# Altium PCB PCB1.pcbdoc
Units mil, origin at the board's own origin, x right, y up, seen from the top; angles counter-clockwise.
Board outline 3110 x 3190 mil, 2 copper layers (Top Layer, Bottom Layer); 7 components, 5 nets, 42 pads, 0 vias.
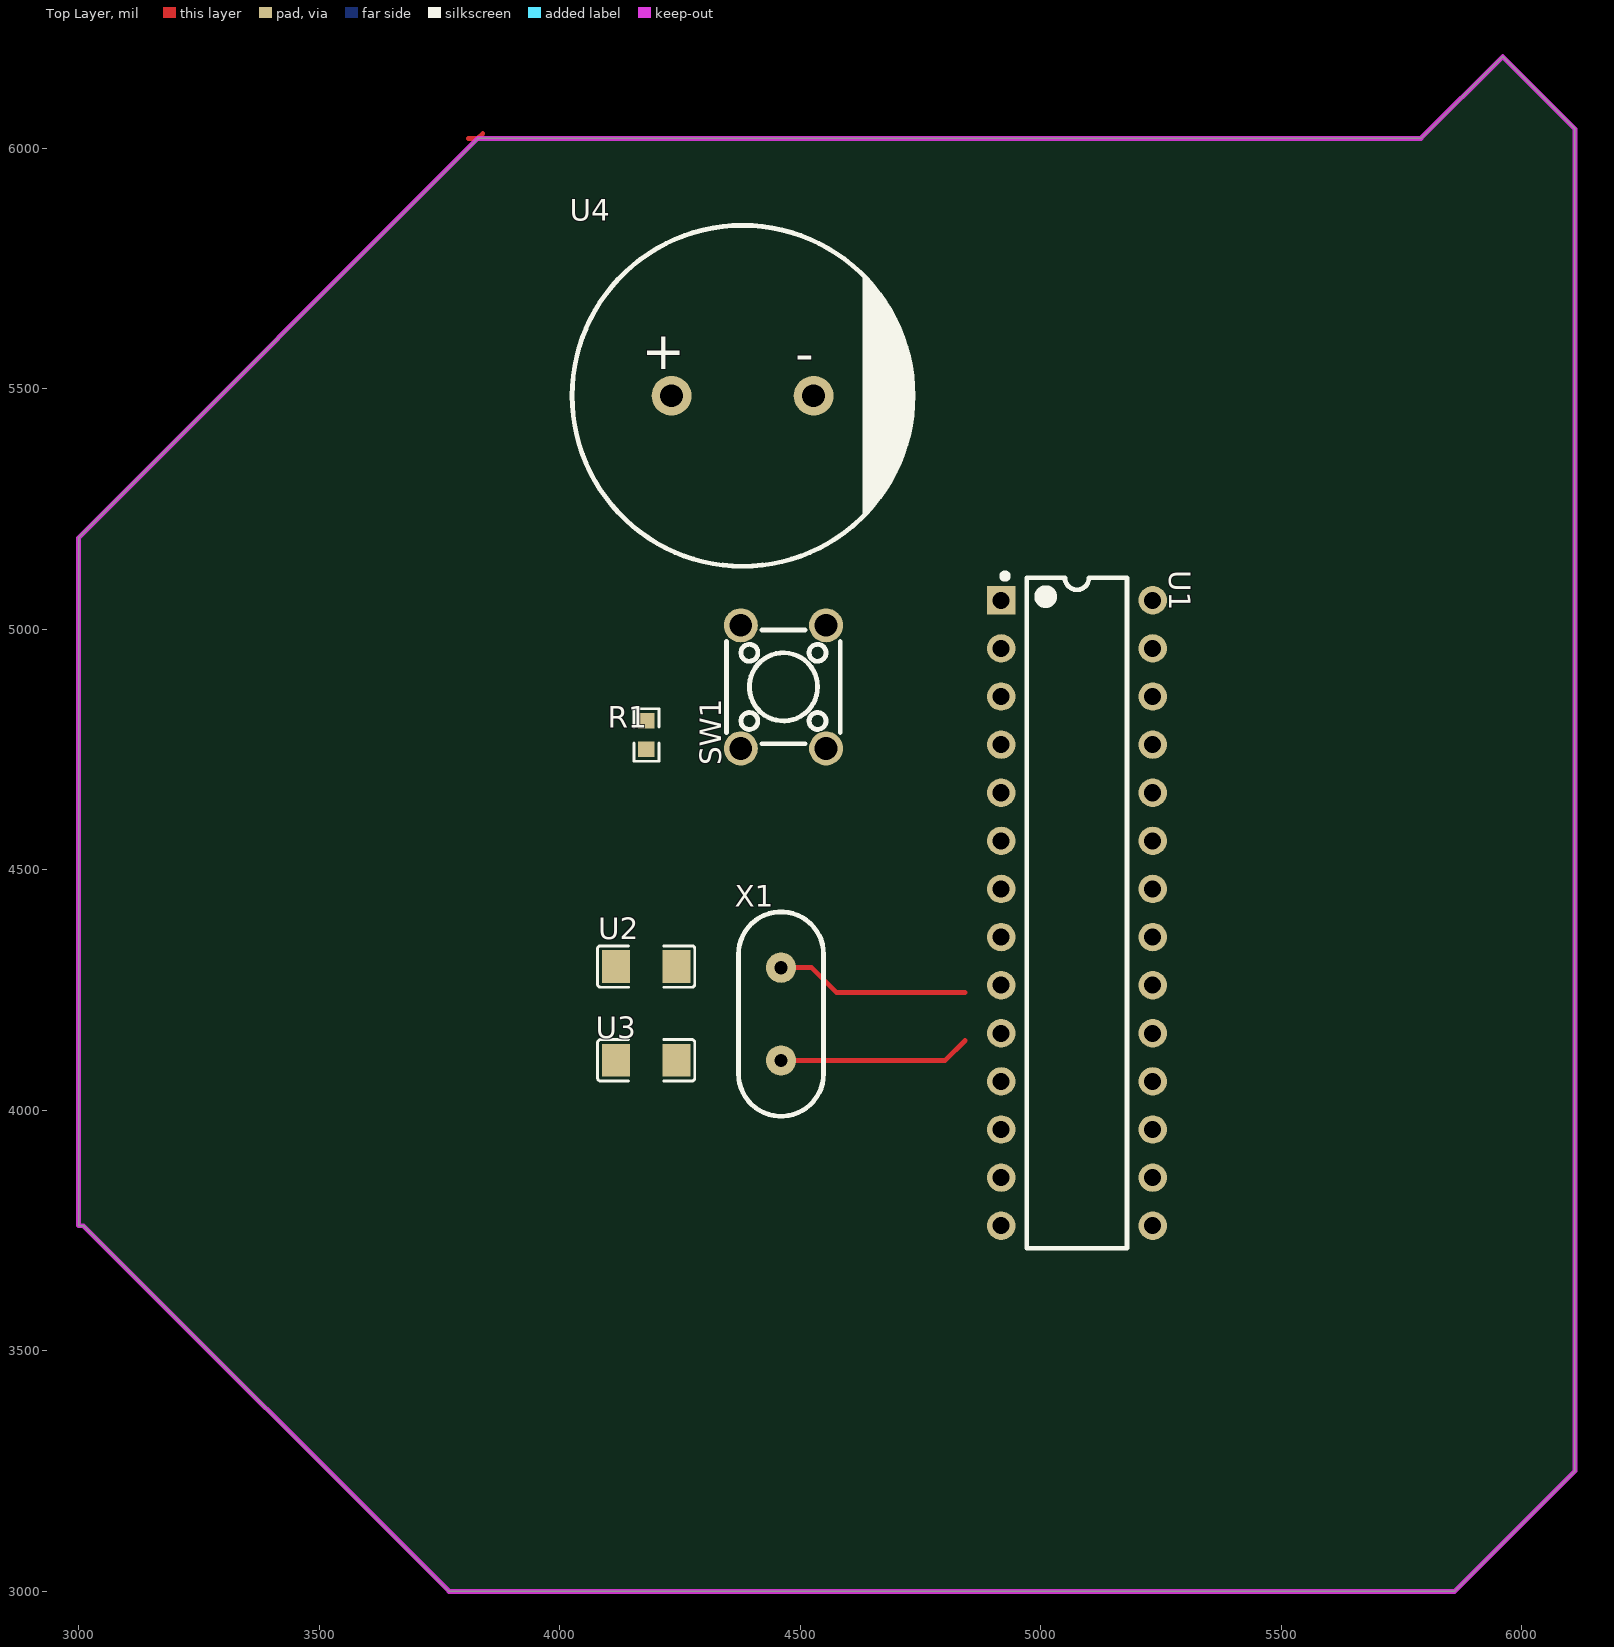
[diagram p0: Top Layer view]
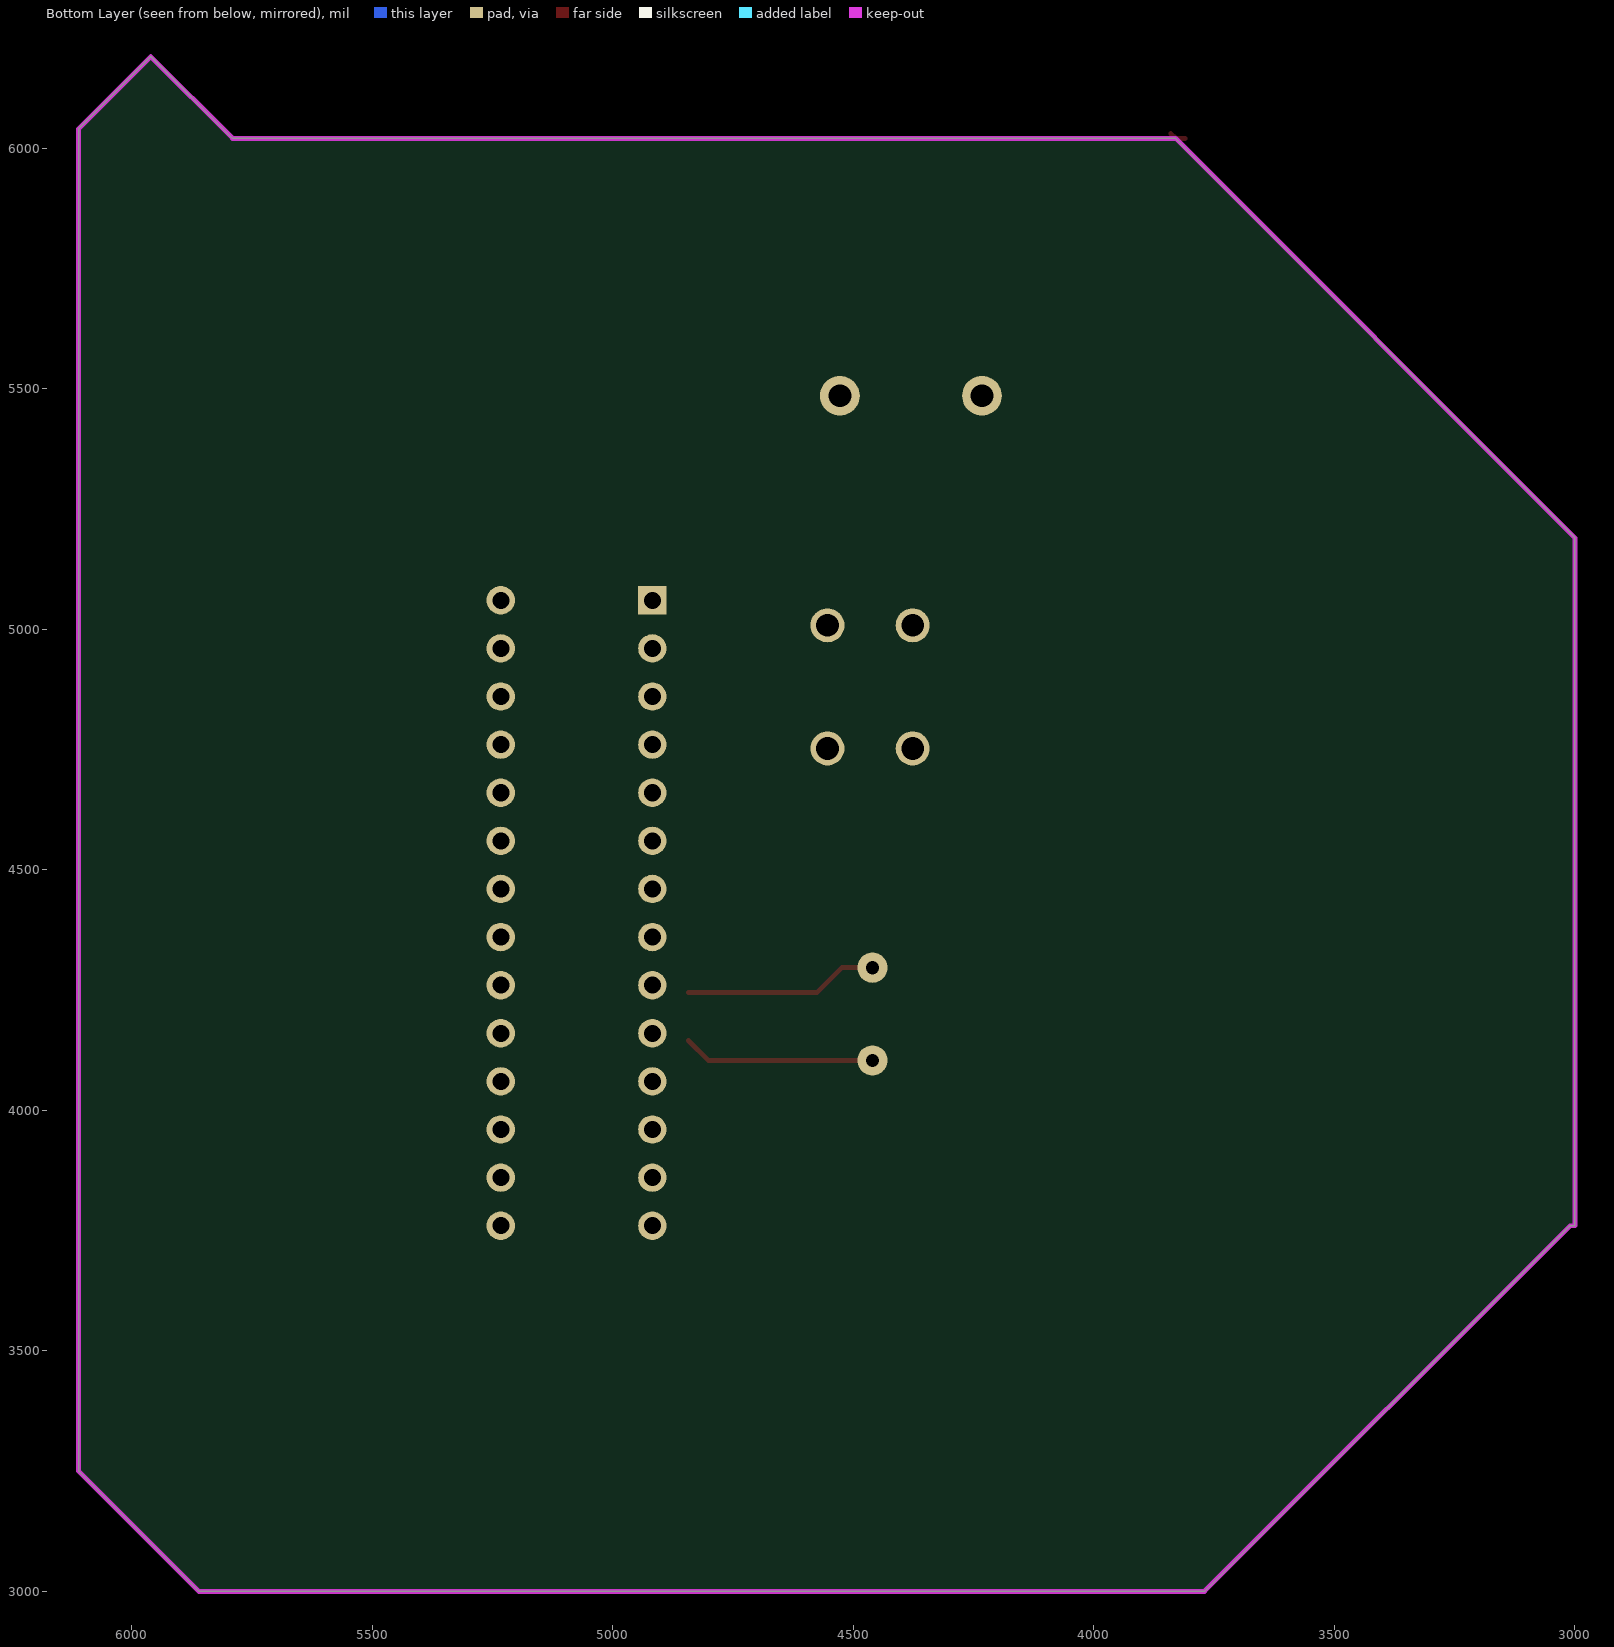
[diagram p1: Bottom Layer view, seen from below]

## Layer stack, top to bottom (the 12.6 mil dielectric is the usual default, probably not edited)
Top Layer: signal copper (thickness not stored)
Dielectric: dielectric 12.6, FR-4, Dk 4.8
Bottom Layer: signal copper (thickness not stored)

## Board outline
3000,5190 3830,6020 5790,6020 5960,6190 6110,6040 6110,3250 5860,3000 3770,3000 3010,3760 3000,3760

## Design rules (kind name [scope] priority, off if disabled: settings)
BoardOutlineClearance copperThickness1oz [All] p0: genericclearance=10 ignorepadtopadclearanceinfootprint=FALSE except(0: Arc-SplitContinuation Track-SplitContinuation SMDPad-SplitContinuation THPad-SplitContinuation Via-SplitContinuation Fill-SplitContinuation Poly-SplitContinuation Region-SplitContinuation Text-SplitContinuation; 6: Track-CutoutEdge SMDPad-CutoutEdge THPad-CutoutEdge Via-CutoutEdge Region-CutoutEdge; 11.8: Track-OutlineEdge SMDPad-OutlineEdge THPad-OutlineEdge Via-OutlineEdge Fill-OutlineEdge Region-OutlineEdge Poly-OutlineEdge Text-OutlineEdge Fill-CutoutEdge)
BoardOutlineClearance copperThickness2oz [All] p0: genericclearance=10 ignorepadtopadclearanceinfootprint=FALSE except(0: Arc-SplitContinuation Track-SplitContinuation SMDPad-SplitContinuation THPad-SplitContinuation Via-SplitContinuation Fill-SplitContinuation Poly-SplitContinuation Region-SplitContinuation Text-SplitContinuation; 6: Track-CutoutEdge SMDPad-CutoutEdge THPad-CutoutEdge Via-CutoutEdge Region-CutoutEdge; 11.8: Track-OutlineEdge SMDPad-OutlineEdge THPad-OutlineEdge Via-OutlineEdge Fill-OutlineEdge Region-OutlineEdge Poly-OutlineEdge Text-OutlineEdge Fill-CutoutEdge)
Clearance copperThickness1oz [(InNet('$1N627') OR InNet('VCC') OR InNet('GND') OR InNet('$1N402') OR InNet('$1N409'))] p1: gap=7 ignorepadtopadclearanceinfootprint=FALSE except(4: Track-Track; 6: Track-SMDPad SMDPad-SMDPad Track-THPad SMDPad-THPad THPad-THPad Track-Via SMDPad-Via THPad-Via Via-Via SMDPad-Fill THPad-Fill Via-Fill Fill-Fill Track-Region SMDPad-Region THPad-Region Via-Region Region-Region Track-Poly SMDPad-Poly THPad-Poly Via-Poly Fill-Poly Region-Poly Poly-Poly Track-Text SMDPad-Text THPad-Text Via-Text Fill-Text Region-Text Poly-Text Text-Text; 6.9: Track-Hole SMDPad-Hole THPad-Hole Via-Hole Fill-Hole Region-Hole Poly-Hole Text-Hole Sheet-Hole; 11.8: Track-Fill Fill-Region Track-Sheet SMDPad-Sheet THPad-Sheet Via-Sheet Fill-Sheet Region-Sheet Poly-Sheet Text-Sheet)
Clearance copperThickness2oz [All] p1: gap=7 ignorepadtopadclearanceinfootprint=FALSE except(6: Track-SMDPad SMDPad-SMDPad Track-THPad SMDPad-THPad THPad-THPad Track-Via SMDPad-Via THPad-Via Via-Via SMDPad-Fill THPad-Fill Via-Fill Fill-Fill Track-Region SMDPad-Region THPad-Region Via-Region Region-Region Track-Poly SMDPad-Poly THPad-Poly Via-Poly Fill-Poly Region-Poly Poly-Poly Track-Text SMDPad-Text THPad-Text Via-Text Fill-Text Region-Text Poly-Text Text-Text; 6.9: Track-Hole SMDPad-Hole THPad-Hole Via-Hole Fill-Hole Region-Hole Poly-Hole Text-Hole Sheet-Hole; 8: Track-Track; 11.8: Track-Fill Fill-Region Track-Sheet SMDPad-Sheet THPad-Sheet Via-Sheet Fill-Sheet Region-Sheet Poly-Sheet Text-Sheet)
DiffPairsRouting differentialPair [All] p1: maxuncoupledlength=10 minlimit=6 maxlimit=6 mostfreqgap=6 toplayer_minwidth=5 toplayer_prefwidth=10 toplayer_maxwidth=100 bottomlayer_minwidth=5 bottomlayer_prefwidth=10 bottomlayer_maxwidth=100
PasteMaskExpansion pasteMaskExpansion [All] p1: expansion=0
PlaneConnect innerPlane [All] p1: planeconnectstyle=Relief reliefexpansion=20 reliefentries=4 reliefconductorwidth=10 reliefairgap=10
PolygonConnect copperRegion [All] p1: connectstyle=Relief reliefentries=4 reliefconductorwidth=10 polygonreliefangle="90 Angle" airgapwidth=10
RoutingVias viaSize [All] p1: viastyle="Through Hole" holewidth=12.0078 minholewidth=11.811 maxholewidth=248.0314 width=24.0158 minwidth=19.685 maxwidth=393.7008
SolderMaskExpansion solderMaskExpansion [All] p1: useseparateexpansions=TRUE expansion=2 expansionbottom=2
Width copperThickness1oz [All] p1: maxlimit=100 minlimit=5 preferedwidth=10
Width copperThickness2oz [All] p1: maxlimit=100 minlimit=8 preferedwidth=10

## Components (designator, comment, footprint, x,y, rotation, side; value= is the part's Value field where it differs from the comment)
R1 "1k" R0603 4180,4780 r270 top
SW1 "Key_TH_6x6x6" SW-TH_4P-L6.0-W6.0-P4.50-LS6.5 4465,4880 r90 top
U1 "ATMEGA328P-PU" DIP-28_L34.6-W7.3-P2.54-LS10.2-BL 5075,4410 r270 top
U2 "FCC1206N220J102DT" C1206 4179.73,4298.79 r180 top
U3 "FCC1206N220J102DT" C1206 4179.73,4103.79 r180 top
U4 "10mF/25V" CAP-TH_BD18.0-P7.50-D0.8-FD 4380,5485 r0 top
X1 "X49SD16MSD2SC" OSC-TH_L10.0-W4.5-P5.00 4460,4200 r0 top

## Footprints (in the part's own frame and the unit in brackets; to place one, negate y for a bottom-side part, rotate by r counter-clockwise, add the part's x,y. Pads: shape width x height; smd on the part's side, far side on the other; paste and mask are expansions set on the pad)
C1206 [mm]
  rect 1.485x1.728 smd: 1(-1.593,0) 2(1.593,0)
  silkscreen extent -2.56,-1.09 2.56,1.09
CAP-TH_BD18.0-P7.50-D0.8-FD [mm]
  round 2.1 hole 1.2: 1(-3.75,0) 2(3.75,0)
  silkscreen extent -9,-9 9,9
DIP-28_L34.6-W7.3-P2.54-LS10.2-BL [mm]
  rect 1.5x1.5 hole 0.9: 1(-16.51,-4)
  round 1.5 hole 0.9: 2(-13.97,-4) 3(-11.43,-4) 4(-8.89,-4) 5(-6.35,-4) 6(-3.81,-4) 7(-1.27,-4) 8(1.27,-4) 9(3.81,-4) 10(6.35,-4) 11(8.89,-4) 12(11.43,-4) 13(13.97,-4) 14(16.51,-4) 15(16.51,4) 16(13.97,4) 17(11.43,4) 18(8.89,4) 19(6.35,4) 20(3.81,4) 21(1.27,4) 22(-1.27,4) 23(-3.81,4) 24(-6.35,4) 25(-8.89,4) 26(-11.43,4) 27(-13.97,4) 28(-16.51,4)
  silkscreen extent -17.94,-3.95 17.7,2.65
OSC-TH_L10.0-W4.5-P5.00 [mm]
  round 1.6 hole 0.7: 1(0,2.45) 2(0,-2.45)
  silkscreen extent -2.25,-5.39 2.25,5.39
R0603 [mil]
  rect 31.75x34.02 smd: 1(-29.66,0) 2(29.66,0)
  silkscreen extent -55,-26 55,26
SW-TH_4P-L6.0-W6.0-P4.50-LS6.5 [mm]
  round 1.8 hole 1.2: 1(-3.25,2.25) 2(3.25,2.25) 3(-3.25,-2.25) 4(3.25,-2.25)
  silkscreen extent -3,-3 3,3

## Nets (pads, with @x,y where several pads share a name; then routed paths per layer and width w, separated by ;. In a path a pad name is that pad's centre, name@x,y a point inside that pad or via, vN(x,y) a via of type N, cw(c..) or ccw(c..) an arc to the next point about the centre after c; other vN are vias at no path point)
$1N402: U1.9 U2.1 X1.1 | length 403.8
  Top Layer w10: X1.1 4523.54,4296.46 4575,4245 4842.52,4245
$1N409: U1.10 U3.1 X1.2 | length 399.7
  Top Layer w10: X1.2 4801.06,4103.54 4842.52,4145
$1N627: R1.2 SW1.1 U1.1
GND: SW1.3 U2.2 U3.2 U4.2
VCC: R1.1 U4.1
pads on no net: SW1.2 SW1.4 U1.2 U1.3 U1.4 U1.5 U1.6 U1.7 U1.8 U1.11 U1.12 U1.13 U1.14 U1.15 U1.16 U1.17 U1.18 U1.19 U1.20 U1.21 U1.22 U1.23 U1.24 U1.25 U1.26 U1.27 U1.28
copper on no net: | length 34.1
  Top Layer w10: 3810,6020 3830,6020 3840,6030

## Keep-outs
Board Outline Layer:
  the board outline again, w10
